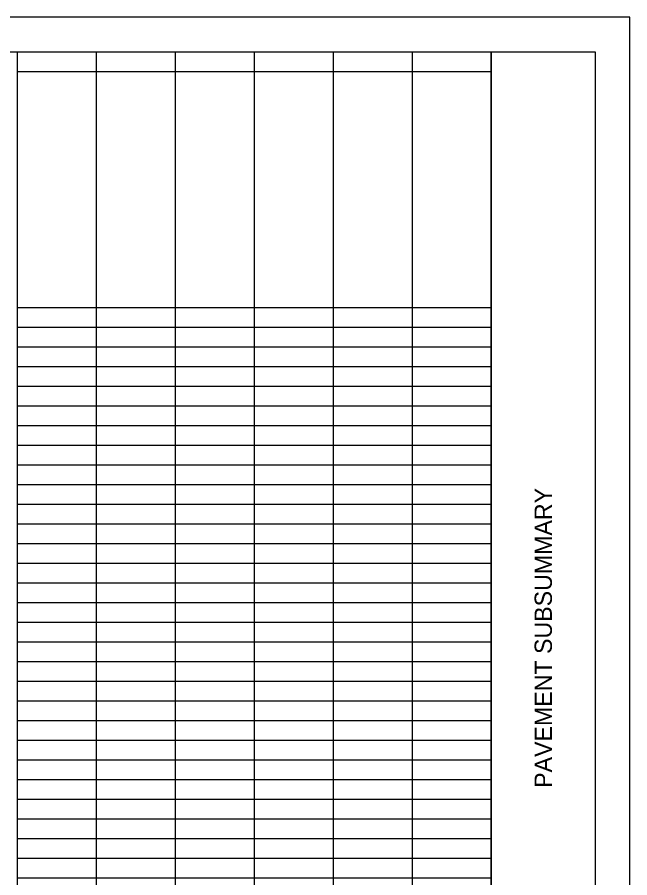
# Model space of a CAD drawing. Extents: x 0 to 34, y 0 to 22.
# Drawn here: x 25.15 to 34, y 9.58 to 22 of the extents above; entities that cross this region are included whole.
import ezdxf

# ---------------------------------------------------------------- set-up
doc = ezdxf.new("R2010")
doc.units = 0
for name, color, linetype in [('SH_Border', 7, 'Continuous'), ('SH_Cut_Line', 7, 'Continuous'), ('SH_Data', 7, 'Continuous'), ('SH_Text', 7, 'Continuous')]:
    doc.layers.add(name, color=color, linetype=linetype)

msp = doc.modelspace()

# ---------------------------------------------------------------- linework, layer by layer
at = {"layer": 'SH_Border'}
msp.add_line((32, 0.5), (32, 21.5), dxfattribs=at)
msp.add_lwpolyline([(1.5, 21.5), (33.5, 21.5), (33.5, 0.5), (1.5, 0.5)], close=True, dxfattribs=at)
at = {"layer": 'SH_Cut_Line'}
msp.add_lwpolyline([(0, 0), (34, 0), (34, 22), (0, 22)], close=True, dxfattribs=at)
at = {"layer": 'SH_Text'}
for p, q in [((25.152, 21.5), (27.435, 21.5)), ((25.152, 21.5), (25.152, 21.216)), ((26.294, 21.5), (26.294, 21.216)), ((27.435, 21.5), (30.859, 21.5)), ((27.435, 21.5), (27.435, 21.216)), ((28.576, 21.5), (28.576, 21.216)), ((29.717, 21.5), (29.717, 21.216)), ((30.859, 21.5), (32, 21.5)), ((30.859, 21.5), (30.859, 21.216)), ((32, 21.5), (32, 21.216)), ((25.152, 21.216), (27.435, 21.216)), ((25.152, 21.216), (25.152, 20.932)), ((26.294, 21.216), (26.294, 20.932)), ((27.435, 21.216), (30.859, 21.216)), ((27.435, 21.216), (27.435, 20.932)), ((28.576, 21.216), (28.576, 20.932)), ((29.717, 21.216), (29.717, 20.932)), ((30.859, 21.216), (32, 21.216)), ((30.859, 21.216), (30.859, 20.932)), ((32, 21.216), (32, 20.932)), ((25.152, 20.932), (25.152, 20.649)), ((26.294, 20.932), (26.294, 20.649)), ((27.435, 20.932), (27.435, 20.649)), ((28.576, 20.932), (28.576, 20.649)), ((29.717, 20.932), (29.717, 20.649)), ((30.859, 20.932), (30.859, 20.649)), ((32, 20.932), (32, 20.649)), ((25.152, 20.649), (25.152, 20.081)), ((26.294, 20.649), (26.294, 20.081)), ((27.435, 20.649), (27.435, 20.081)), ((28.576, 20.649), (28.576, 20.081)), ((29.717, 20.649), (29.717, 20.081)), ((30.859, 20.649), (30.859, 20.081)), ((32, 20.649), (32, 20.081)), ((25.152, 20.081), (25.152, 19.797)), ((26.294, 20.081), (26.294, 19.797)), ((27.435, 20.081), (27.435, 19.797)), ((28.576, 20.081), (28.576, 19.797)), ((29.717, 20.081), (29.717, 19.797)), ((30.859, 20.081), (30.859, 19.797)), ((32, 20.081), (32, 19.797)), ((25.152, 19.797), (25.152, 19.514)), ((26.294, 19.797), (26.294, 19.514)), ((27.435, 19.797), (27.435, 19.514)), ((28.576, 19.797), (28.576, 19.514)), ((29.717, 19.797), (29.717, 19.514)), ((30.859, 19.797), (30.859, 19.514)), ((32, 19.797), (32, 19.514)), ((25.152, 19.514), (25.152, 19.23)), ((26.294, 19.514), (26.294, 19.23)), ((27.435, 19.514), (27.435, 19.23)), ((28.576, 19.514), (28.576, 19.23)), ((29.717, 19.514), (29.717, 19.23)), ((30.859, 19.514), (30.859, 19.23)), ((32, 19.514), (32, 19.23)), ((25.152, 19.23), (25.152, 18.946)), ((26.294, 19.23), (26.294, 18.946)), ((27.435, 19.23), (27.435, 18.946)), ((28.576, 19.23), (28.576, 18.946)), ((29.717, 19.23), (29.717, 18.946)), ((30.859, 19.23), (30.859, 18.946)), ((32, 19.23), (32, 18.946)), ((25.152, 18.946), (25.152, 18.662)), ((26.294, 18.946), (26.294, 18.662)), ((27.435, 18.946), (27.435, 18.662)), ((28.576, 18.946), (28.576, 18.662)), ((29.717, 18.946), (29.717, 18.662)), ((30.859, 18.946), (30.859, 18.662)), ((32, 18.946), (32, 18.662)), ((25.152, 18.662), (25.152, 18.378)), ((26.294, 18.662), (26.294, 18.378)), ((27.435, 18.662), (27.435, 18.378)), ((28.576, 18.662), (28.576, 18.378)), ((29.717, 18.662), (29.717, 18.378)), ((30.859, 18.662), (30.859, 18.378)), ((32, 18.662), (32, 18.378)), ((25.152, 18.378), (25.152, 18.095)), ((26.294, 18.378), (26.294, 18.095)), ((27.435, 18.378), (27.435, 18.095)), ((28.576, 18.378), (28.576, 18.095)), ((29.717, 18.378), (29.717, 18.095)), ((30.859, 18.378), (30.859, 18.095)), ((32, 18.378), (32, 18.095)), ((25.152, 18.095), (25.152, 17.811)), ((26.294, 18.095), (26.294, 17.811)), ((27.435, 18.095), (27.435, 17.811)), ((28.576, 18.095), (28.576, 17.811)), ((29.717, 18.095), (29.717, 17.811)), ((30.859, 18.095), (30.859, 17.811)), ((32, 18.095), (32, 17.811)), ((25.152, 17.811), (27.435, 17.811)), ((25.152, 17.811), (25.152, 17.527)), ((26.294, 17.811), (26.294, 17.527)), ((27.435, 17.811), (30.859, 17.811)), ((27.435, 17.811), (27.435, 17.527)), ((28.576, 17.811), (28.576, 17.527)), ((29.717, 17.811), (29.717, 17.527)), ((30.859, 17.811), (32, 17.811)), ((30.859, 17.811), (30.859, 17.527)), ((32, 17.811), (32, 17.527)), ((25.152, 17.527), (27.435, 17.527)), ((25.152, 17.527), (25.152, 17.243)), ((26.294, 17.527), (26.294, 17.243)), ((27.435, 17.527), (30.859, 17.527)), ((27.435, 17.527), (27.435, 17.243)), ((28.576, 17.527), (28.576, 17.243)), ((29.717, 17.527), (29.717, 17.243)), ((30.859, 17.527), (32, 17.527)), ((30.859, 17.527), (30.859, 17.243)), ((32, 17.527), (32, 17.243)), ((25.152, 17.243), (27.435, 17.243)), ((25.152, 17.243), (25.152, 16.959)), ((26.294, 17.243), (26.294, 16.959)), ((27.435, 17.243), (30.859, 17.243)), ((27.435, 17.243), (27.435, 16.959)), ((28.576, 17.243), (28.576, 16.959)), ((29.717, 17.243), (29.717, 16.959)), ((30.859, 17.243), (32, 17.243)), ((30.859, 17.243), (30.859, 16.959)), ((32, 17.243), (32, 16.959)), ((25.152, 16.959), (27.435, 16.959)), ((25.152, 16.959), (25.152, 16.676)), ((26.294, 16.959), (26.294, 16.676)), ((27.435, 16.959), (30.859, 16.959)), ((27.435, 16.959), (27.435, 16.676)), ((28.576, 16.959), (28.576, 16.676)), ((29.717, 16.959), (29.717, 16.676)), ((30.859, 16.959), (32, 16.959)), ((30.859, 16.959), (30.859, 16.676)), ((32, 16.959), (32, 16.676)), ((25.152, 16.676), (27.435, 16.676)), ((25.152, 16.676), (25.152, 16.108)), ((26.294, 16.676), (26.294, 16.108)), ((27.435, 16.676), (30.859, 16.676)), ((27.435, 16.676), (27.435, 16.108)), ((28.576, 16.676), (28.576, 16.108)), ((29.717, 16.676), (29.717, 16.108)), ((30.859, 16.676), (32, 16.676)), ((30.859, 16.676), (30.859, 16.108)), ((32, 16.676), (32, 16.108)), ((25.152, 16.392), (27.435, 16.392)), ((27.435, 16.392), (30.859, 16.392)), ((30.859, 16.392), (32, 16.392)), ((25.152, 16.108), (27.435, 16.108)), ((25.152, 16.108), (25.152, 15.824)), ((26.294, 16.108), (26.294, 15.824)), ((27.435, 16.108), (30.859, 16.108)), ((27.435, 16.108), (27.435, 15.824)), ((28.576, 16.108), (28.576, 15.824)), ((29.717, 16.108), (29.717, 15.824)), ((30.859, 16.108), (32, 16.108)), ((30.859, 16.108), (30.859, 15.824)), ((32, 16.108), (32, 15.824)), ((25.152, 15.824), (27.435, 15.824)), ((25.152, 15.824), (25.152, 15.541)), ((26.294, 15.824), (26.294, 15.541)), ((27.435, 15.824), (30.859, 15.824)), ((27.435, 15.824), (27.435, 15.541)), ((28.576, 15.824), (28.576, 15.541)), ((29.717, 15.824), (29.717, 15.541)), ((30.859, 15.824), (32, 15.824)), ((30.859, 15.824), (30.859, 15.541)), ((32, 15.824), (32, 15.541)), ((25.152, 15.541), (27.435, 15.541)), ((25.152, 15.541), (25.152, 15.257)), ((26.294, 15.541), (26.294, 15.257)), ((27.435, 15.541), (30.859, 15.541)), ((27.435, 15.541), (27.435, 15.257)), ((28.576, 15.541), (28.576, 15.257)), ((29.717, 15.541), (29.717, 15.257)), ((30.859, 15.541), (32, 15.541)), ((30.859, 15.541), (30.859, 15.257)), ((32, 15.541), (32, 15.257)), ((25.152, 15.257), (27.435, 15.257)), ((25.152, 15.257), (25.152, 14.689)), ((26.294, 15.257), (26.294, 14.689)), ((27.435, 15.257), (30.859, 15.257)), ((27.435, 15.257), (27.435, 14.689)), ((28.576, 15.257), (28.576, 14.689)), ((29.717, 15.257), (29.717, 14.689)), ((30.859, 15.257), (32, 15.257)), ((30.859, 15.257), (30.859, 14.689)), ((32, 15.257), (32, 14.689)), ((25.152, 14.973), (27.435, 14.973)), ((27.435, 14.973), (30.859, 14.973)), ((30.859, 14.973), (32, 14.973)), ((25.152, 14.689), (27.435, 14.689)), ((25.152, 14.689), (25.152, 14.405)), ((26.294, 14.689), (26.294, 14.405)), ((27.435, 14.689), (30.859, 14.689)), ((27.435, 14.689), (27.435, 14.405)), ((28.576, 14.689), (28.576, 14.405)), ((29.717, 14.689), (29.717, 14.405)), ((30.859, 14.689), (32, 14.689)), ((30.859, 14.689), (30.859, 14.405)), ((32, 14.689), (32, 14.405)), ((25.152, 14.405), (27.435, 14.405)), ((25.152, 14.405), (25.152, 14.122)), ((26.294, 14.405), (26.294, 14.122)), ((27.435, 14.405), (30.859, 14.405)), ((27.435, 14.405), (27.435, 14.122)), ((28.576, 14.405), (28.576, 14.122)), ((29.717, 14.405), (29.717, 14.122)), ((30.859, 14.405), (32, 14.405)), ((30.859, 14.405), (30.859, 14.122)), ((32, 14.405), (32, 14.122)), ((25.152, 14.122), (27.435, 14.122)), ((25.152, 14.122), (25.152, 13.838)), ((26.294, 14.122), (26.294, 13.838)), ((27.435, 14.122), (30.859, 14.122)), ((27.435, 14.122), (27.435, 13.838)), ((28.576, 14.122), (28.576, 13.838)), ((29.717, 14.122), (29.717, 13.838)), ((30.859, 14.122), (32, 14.122)), ((30.859, 14.122), (30.859, 13.838)), ((32, 14.122), (32, 13.838)), ((25.152, 13.838), (27.435, 13.838)), ((25.152, 13.838), (25.152, 12.986)), ((26.294, 13.838), (26.294, 12.986)), ((27.435, 13.838), (30.859, 13.838)), ((27.435, 13.838), (27.435, 12.986)), ((28.576, 13.838), (28.576, 12.986)), ((29.717, 13.838), (29.717, 12.986)), ((30.859, 13.838), (32, 13.838)), ((30.859, 13.838), (30.859, 12.986)), ((32, 13.838), (32, 12.986)), ((25.152, 13.554), (27.435, 13.554)), ((27.435, 13.554), (30.859, 13.554)), ((30.859, 13.554), (32, 13.554)), ((25.152, 13.27), (27.435, 13.27)), ((27.435, 13.27), (30.859, 13.27)), ((30.859, 13.27), (32, 13.27)), ((25.152, 12.986), (27.435, 12.986)), ((25.152, 12.986), (25.152, 12.703)), ((26.294, 12.986), (26.294, 12.703)), ((27.435, 12.986), (30.859, 12.986)), ((27.435, 12.986), (27.435, 12.703)), ((28.576, 12.986), (28.576, 12.703)), ((29.717, 12.986), (29.717, 12.703)), ((30.859, 12.986), (32, 12.986)), ((30.859, 12.986), (30.859, 12.703)), ((32, 12.986), (32, 12.703)), ((25.152, 12.703), (27.435, 12.703)), ((25.152, 12.703), (25.152, 11.568)), ((26.294, 12.703), (26.294, 11.568)), ((27.435, 12.703), (30.859, 12.703)), ((27.435, 12.703), (27.435, 11.568)), ((28.576, 12.703), (28.576, 11.568)), ((29.717, 12.703), (29.717, 11.568)), ((30.859, 12.703), (32, 12.703)), ((30.859, 12.703), (30.859, 11.568)), ((32, 12.703), (32, 11.568)), ((25.152, 12.419), (27.435, 12.419)), ((27.435, 12.419), (30.859, 12.419)), ((30.859, 12.419), (32, 12.419)), ((25.152, 12.135), (27.435, 12.135)), ((27.435, 12.135), (30.859, 12.135)), ((30.859, 12.135), (32, 12.135)), ((25.152, 11.851), (27.435, 11.851)), ((27.435, 11.851), (30.859, 11.851)), ((30.859, 11.851), (32, 11.851)), ((25.152, 11.568), (27.435, 11.568)), ((25.152, 11.568), (25.152, 11.284)), ((26.294, 11.568), (26.294, 11.284)), ((27.435, 11.568), (30.859, 11.568)), ((27.435, 11.568), (27.435, 11.284)), ((28.576, 11.568), (28.576, 11.284)), ((29.717, 11.568), (29.717, 11.284)), ((30.859, 11.568), (32, 11.568)), ((30.859, 11.568), (30.859, 11.284)), ((32, 11.568), (32, 11.284)), ((25.152, 11.284), (27.435, 11.284)), ((25.152, 11.284), (25.152, 10.149)), ((26.294, 11.284), (26.294, 10.149)), ((27.435, 11.284), (30.859, 11.284)), ((27.435, 11.284), (27.435, 10.149)), ((28.576, 11.284), (28.576, 10.149)), ((29.717, 11.284), (29.717, 10.149)), ((30.859, 11.284), (32, 11.284)), ((30.859, 11.284), (30.859, 10.149)), ((32, 11.284), (32, 10.149)), ((25.152, 11), (27.435, 11)), ((27.435, 11), (30.859, 11)), ((30.859, 11), (32, 11)), ((25.152, 10.716), (27.435, 10.716)), ((27.435, 10.716), (30.859, 10.716)), ((30.859, 10.716), (32, 10.716)), ((25.152, 10.432), (27.435, 10.432)), ((27.435, 10.432), (30.859, 10.432)), ((30.859, 10.432), (32, 10.432)), ((25.152, 10.149), (27.435, 10.149)), ((25.152, 10.149), (25.152, 9.581)), ((26.294, 10.149), (26.294, 9.581)), ((27.435, 10.149), (30.859, 10.149)), ((27.435, 10.149), (27.435, 9.581)), ((28.576, 10.149), (28.576, 9.581)), ((29.717, 10.149), (29.717, 9.581)), ((30.859, 10.149), (32, 10.149)), ((30.859, 10.149), (30.859, 9.581)), ((32, 10.149), (32, 9.581)), ((25.152, 9.865), (27.435, 9.865)), ((27.435, 9.865), (30.859, 9.865)), ((30.859, 9.865), (32, 9.865)), ((25.152, 9.581), (27.435, 9.581)), ((25.152, 9.581), (25.152, 9.297)), ((26.294, 9.581), (26.294, 9.297)), ((27.435, 9.581), (30.859, 9.581)), ((27.435, 9.581), (27.435, 9.297)), ((28.576, 9.581), (28.576, 9.297)), ((29.717, 9.581), (29.717, 9.297)), ((30.859, 9.581), (32, 9.581)), ((30.859, 9.581), (30.859, 9.297)), ((32, 9.581), (32, 9.297))]:
    msp.add_line(p, q, dxfattribs=at)

# ---------------------------------------------------------------- texts
at = {"layer": 'SH_Data'}
msp.add_text('PAVEMENT SUBSUMMARY', height=0.25, rotation=90, dxfattribs=at).set_placement((32.875, 10.879))

doc.saveas('drawing.dxf')
